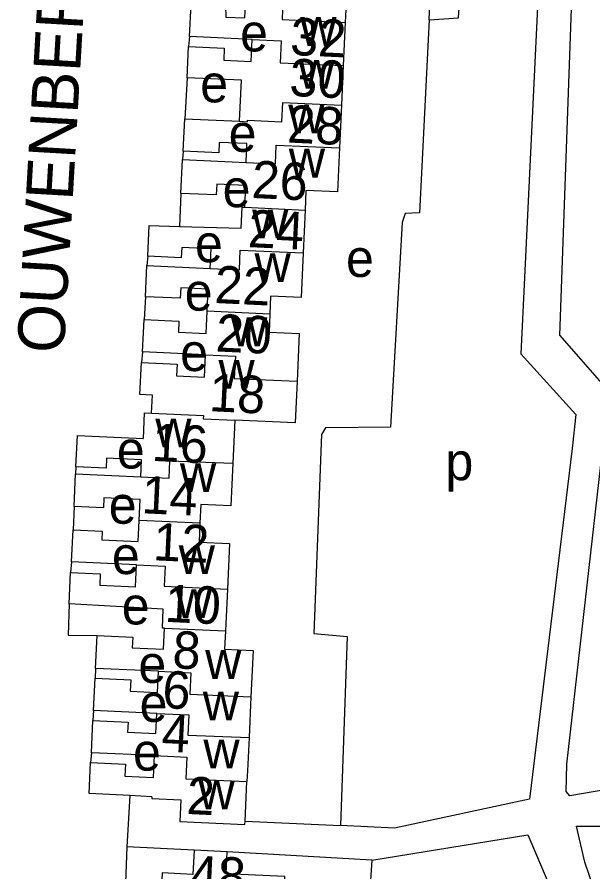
# Model space of a CAD drawing. Extents: x 163026 to 166241, y 382475 to 384501.
# Drawn here: x 164523.5 to 164584.9, y 383742 to 383833.2 of the extents above; entities that cross this region are included whole.
import ezdxf

# ---------------------------------------------------------------- set-up
doc = ezdxf.new("R2010")
doc.units = 0
for name, color, linetype in [('BLT_Basislijn', 7, 'Continuous'), ('BLT_Bebouwing', 7, 'Continuous'), ('BLT_Centroide', 7, 'Continuous'), ('BLT_Huisnummer', 7, 'Continuous'), ('BLT_Huisnummer_ tussenligend', 7, 'Continuous'), ('BLT_Onderverdeling_panden', 7, 'Continuous'), ('BLT_Straatnaam', 7, 'Continuous')]:
    doc.layers.add(name, color=color, linetype=linetype)

msp = doc.modelspace()

# ---------------------------------------------------------------- linework, layer by layer
at = {"layer": 'BLT_Basislijn'}
for p, q in [((164541.896, 383831.104), (164541.781, 383830.036)), ((164541.629, 383826.713), (164541.396, 383822.332)), ((164541.227, 383818.876), (164541.132, 383817.996)), ((164540.975, 383814.376), (164540.836, 383810.848)), ((164537.454, 383807.67), (164537.354, 383806.661)), ((164537.203, 383803.35), (164537.052, 383800.912)), ((164536.895, 383797.47), (164536.764, 383796.325)), ((164529.782, 383785.201), (164529.739, 383784.433)), ((164529.58, 383780.952), (164529.466, 383778.486)), ((164529.309, 383775.064), (164529.211, 383773.926)), ((164531.878, 383763.683), (164531.818, 383762.65)), ((164531.66, 383759.183), (164531.589, 383758.124)), ((164531.432, 383754.691), (164531.332, 383753.652)), ((164535.525, 383750.12), (164535.214, 383744.654)), ((164547.826, 383747.404), (164557.994, 383746.91)), ((164535.214, 383744.654), (164534.789, 383734.184)), ((164542.379, 383744.282), (164535.214, 383744.654)), ((164561.354, 383743.226), (164545.927, 383744.118))]:
    msp.add_line(p, q, dxfattribs=at)
for points in [[(164589.125, 383751.219), (164582.465, 383750.072), (164582.095, 383750.55), (164582.146, 383753.456), (164586.671, 383793.224), (164581.394, 383799.235), (164582.783, 383838.098), (164573.158, 383847.436), (164570.309, 383851.598)], [(164567.479, 383832.909), (164568.008, 383845.874), (164563.833, 383846.129)], [(164567.479, 383832.909), (164570.609, 383833.094), (164571.259, 383842.802), (164571.852, 383842.833), (164579.118, 383836.504), (164577.251, 383797.24), (164583.102, 383790.77), (164582.732, 383787.137), (164578.162, 383749.721), (164563.757, 383746.63), (164557.994, 383746.91)], [(164567.479, 383832.909), (164566.447, 383812.283), (164564.917, 383812.238), (164564.598, 383811.269), (164563.342, 383789.419), (164556.395, 383789.368), (164555.98, 383788.654), (164555.164, 383767.428), (164558.721, 383767.078), (164557.994, 383746.91)], [(164529.058, 383770.583), (164528.949, 383767.235), (164532.038, 383767.181)], [(164584.939, 383718.245), (164586.206, 383736.75), (164584.064, 383743.009), (164583.198, 383746.853), (164590.249, 383746.86)], [(164561.354, 383743.226), (164577.984, 383745.916), (164582.222, 383736.004), (164581.211, 383719.232)], [(164561.354, 383743.226), (164560.117, 383724.499), (164558.492, 383687.931)]]:
    msp.add_lwpolyline(points, dxfattribs=at)
at = {"layer": 'BLT_Bebouwing'}
for p, q in [((164558.717, 383837.266), (164558.503, 383832.608)), ((164558.503, 383832.608), (164558.292, 383828.002)), ((164541.629, 383826.713), (164541.781, 383830.036)), ((164558.292, 383828.002), (164558.098, 383823.771)), ((164558.098, 383823.771), (164557.89, 383819.228)), ((164541.227, 383818.876), (164541.396, 383822.332)), ((164540.975, 383814.376), (164541.132, 383817.996)), ((164554.221, 383812.596), (164554.011, 383808.024)), ((164537.203, 383803.35), (164537.354, 383806.661)), ((164536.895, 383797.47), (164537.052, 383800.912)), ((164536.608, 383792.907), (164536.764, 383796.325)), ((164546.734, 383790.167), (164546.525, 383785.595)), ((164529.58, 383780.952), (164529.739, 383784.433)), ((164529.309, 383775.064), (164529.466, 383778.486)), ((164529.058, 383770.583), (164529.211, 383773.926)), ((164545.932, 383772.149), (164545.73, 383767.679)), ((164531.878, 383763.683), (164532.038, 383767.181)), ((164531.66, 383759.183), (164531.818, 383762.65)), ((164548.44, 383760.65), (164548.24, 383756.32)), ((164531.432, 383754.691), (164531.589, 383758.124)), ((164548.24, 383756.32), (164548.082, 383752.767)), ((164548.082, 383752.767), (164548.022, 383751.602)), ((164547.826, 383747.404), (164548.022, 383751.602)), ((164537.883, 383750), (164535.525, 383750.12)), ((164545.927, 383744.118), (164542.379, 383744.282))]:
    msp.add_line(p, q, dxfattribs=at)
for points in [[(164545.734, 383834.376), (164545.771, 383833.184), (164547.787, 383833.092), (164547.887, 383835.272)], [(164541.896, 383831.104), (164542.053, 383834.545), (164545.734, 383834.376)], [(164548.576, 383830.798), (164541.896, 383831.104)], [(164541.781, 383830.036), (164545.598, 383829.861), (164545.54, 383828.588), (164548.469, 383828.454), (164548.576, 383830.798)], [(164547.227, 383822.064), (164547.427, 383826.448), (164541.629, 383826.713)], [(164541.396, 383822.332), (164547.227, 383822.064)], [(164547.925, 383817.675), (164548.015, 383819.679), (164545.063, 383819.814), (164545.013, 383818.718), (164541.227, 383818.876)], [(164557.89, 383819.228), (164557.676, 383814.541), (164554.317, 383814.695), (164554.221, 383812.596)], [(164541.132, 383817.996), (164547.925, 383817.675)], [(164547.781, 383812.89), (164547.888, 383815.22), (164544.805, 383815.361), (164544.752, 383814.203), (164540.975, 383814.376)], [(164540.836, 383810.848), (164547.422, 383810.651), (164547.525, 383812.902), (164547.781, 383812.89)], [(164537.454, 383807.67), (164537.604, 383810.945), (164540.836, 383810.848)], [(164544.089, 383806.353), (164544.186, 383808.464), (164541.066, 383808.607), (164541.016, 383807.507), (164537.454, 383807.67)], [(164554.011, 383808.024), (164553.795, 383803.274), (164550.551, 383803.422), (164550.462, 383801.494)], [(164537.354, 383806.661), (164544.089, 383806.353)], [(164543.782, 383801.801), (164543.89, 383804.157), (164540.951, 383804.291), (164540.9, 383803.181), (164537.203, 383803.35)], [(164537.052, 383800.912), (164540.769, 383800.742), (164540.714, 383799.551), (164543.673, 383799.416), (164543.782, 383801.801)], [(164550.462, 383801.494), (164550.374, 383799.567), (164553.596, 383799.42), (164553.363, 383794.332)], [(164543.606, 383797.163), (164536.895, 383797.47)], [(164536.764, 383796.325), (164540.576, 383796.15), (164540.52, 383794.914), (164543.497, 383794.778), (164543.606, 383797.163)], [(164553.363, 383794.332), (164553.16, 383789.873), (164546.734, 383790.167)], [(164537.845, 383790.93), (164537.933, 383792.846), (164536.608, 383792.907)], [(164529.782, 383785.201), (164529.939, 383788.549), (164536.971, 383788.224), (164537.096, 383790.964), (164537.845, 383790.93)], [(164536.695, 383784.115), (164536.781, 383785.96), (164533.049, 383786.13), (164533, 383785.057), (164529.782, 383785.201)], [(164546.525, 383785.595), (164546.316, 383781.026), (164543.089, 383781.174), (164542.997, 383779.173)], [(164529.739, 383784.433), (164536.695, 383784.115)], [(164536.509, 383779.47), (164536.611, 383781.7), (164532.766, 383781.876), (164532.717, 383780.809), (164529.58, 383780.952)], [(164529.466, 383778.486), (164532.579, 383778.344), (164532.536, 383777.405), (164536.406, 383777.228), (164536.509, 383779.47)], [(164542.997, 383779.173), (164542.906, 383777.172), (164546.157, 383777.023), (164545.932, 383772.149)], [(164529.211, 383773.926), (164532.367, 383773.782), (164532.312, 383772.569), (164536.147, 383772.393), (164536.255, 383774.745)], [(164536.255, 383774.745), (164529.309, 383775.064)], [(164539.229, 383767.978), (164538.995, 383767.988), (164539.088, 383770.011), (164529.058, 383770.583)], [(164532.038, 383767.181), (164535.833, 383767.008), (164535.781, 383765.892), (164539.126, 383765.739), (164539.229, 383767.978)], [(164545.73, 383767.679), (164545.642, 383765.747), (164548.67, 383765.608), (164548.44, 383760.65)], [(164538.595, 383763.375), (164531.878, 383763.683)], [(164531.818, 383762.65), (164535.628, 383762.476), (164535.572, 383761.243), (164538.492, 383761.11), (164538.595, 383763.375)], [(164538.395, 383758.875), (164531.66, 383759.183)], [(164531.589, 383758.124), (164535.34, 383757.952), (164535.291, 383756.867), (164538.299, 383756.729), (164538.395, 383758.875)], [(164538.157, 383754.384), (164531.432, 383754.691)], [(164535.525, 383750.12), (164531.175, 383750.341), (164531.332, 383753.652)], [(164531.332, 383753.652), (164535.061, 383753.481), (164535.002, 383752.201), (164538.051, 383752.061), (164538.157, 383754.384)], [(164537.883, 383750), (164537.875, 383749.791), (164540.979, 383749.648), (164540.874, 383747.36), (164547.808, 383747.032), (164547.826, 383747.404)], [(164542.379, 383744.282), (164542.26, 383741.707), (164538.964, 383741.859), (164538.859, 383739.588), (164542.073, 383739.44)], [(164551.836, 383736.616), (164552.06, 383741.489), (164545.819, 383741.777), (164545.927, 383744.118)]]:
    msp.add_lwpolyline(points, dxfattribs=at)
at = {"layer": 'BLT_Onderverdeling_panden'}
for p, q in [((164547.781, 383812.89), (164554.221, 383812.596)), ((164550.462, 383801.494), (164543.782, 383801.801)), ((164542.997, 383779.173), (164536.509, 383779.47)), ((164539.229, 383767.978), (164545.73, 383767.679))]:
    msp.add_line(p, q, dxfattribs=at)
for points in [[(164547.887, 383835.272), (164551.863, 383835.096), (164551.763, 383832.913), (164558.503, 383832.608)], [(164548.576, 383830.798), (164551.66, 383830.659), (164551.552, 383828.313), (164558.292, 383828.002)], [(164547.227, 383822.064), (164548.076, 383822.025), (164548.083, 383822.182), (164551.739, 383822.014), (164551.832, 383824.057), (164558.098, 383823.771)], [(164547.925, 383817.675), (164551.058, 383817.527), (164551.15, 383819.536), (164557.89, 383819.228)], [(164544.089, 383806.353), (164547.214, 383806.214), (164547.312, 383808.325), (164554.011, 383808.024)], [(164543.606, 383797.163), (164546.786, 383797.02), (164546.675, 383794.636), (164553.363, 383794.332)], [(164537.845, 383790.93), (164543.371, 383790.677), (164543.354, 383790.32), (164546.734, 383790.167)], [(164536.695, 383784.115), (164539.716, 383783.976), (164539.799, 383785.822), (164546.525, 383785.595)], [(164536.255, 383774.745), (164539.296, 383774.605), (164539.199, 383772.456), (164545.932, 383772.149)], [(164538.595, 383763.375), (164542.029, 383763.216), (164541.924, 383760.951), (164548.44, 383760.65)], [(164538.395, 383758.875), (164541.821, 383758.717), (164541.722, 383756.576), (164548.24, 383756.32)], [(164538.157, 383754.384), (164541.613, 383754.228), (164541.505, 383751.901), (164548.022, 383751.602)]]:
    msp.add_lwpolyline(points, dxfattribs=at)

# ---------------------------------------------------------------- texts
at = {"layer": 'BLT_Centroide'}
for s, p in [('w', (164553.708, 383830.106)), ('e', (164547.288, 383829.521)), ('w', (164553.515, 383825.548)), ('e', (164543.035, 383824.085)), ('w', (164552.424, 383820.781)), ('e', (164546.068, 383818.811)), ('w', (164552.488, 383816.062)), ('e', (164545.426, 383812.902)), ('w', (164548.572, 383809.562)), ('e', (164542.473, 383807.027)), ('e', (164558.586, 383805.455)), ('w', (164548.829, 383804.906)), ('e', (164541.382, 383801.86)), ('w', (164546.325, 383798.062)), ('e', (164540.895, 383795.415)), ('w', (164544.984, 383793.531)), ('w', (164538.242, 383787.281)), ('e', (164534.141, 383785.017)), ('p', (164569.196, 383783.766)), ('w', (164540.869, 383782.5)), ('e', (164533.275, 383779.125)), ('e', (164533.615, 383773.752)), ('w', (164540.74, 383773.743)), ('w', (164540.419, 383769.057)), ('e', (164534.66, 383768.38)), ('w', (164543.565, 383762.573)), ('e', (164536.439, 383762.141)), ('e', (164536.568, 383757.981)), ('w', (164543.308, 383758.144)), ('e', (164535.861, 383752.782)), ('w', (164543.372, 383753.008)), ('w', (164542.859, 383748.643))]:
    msp.add_text(s, height=4, dxfattribs=at).set_placement(p)
at = {"layer": 'BLT_Huisnummer'}
for s, rotation, p in [('30', 357.29175, (164552.497, 383824.784)), ('26', 357.29175, (164548.465, 383813.891)), ('22', 357.29175, (164544.506, 383802.683)), ('18', 357.29175, (164543.925, 383791.142)), ('14', 357.29175, (164536.716, 383780.249)), ('10', 357.29175, (164539.195, 383768.663)), ('6', 357.29175, (164538.935, 383759.459)), ('2', 357.29175, (164541.52, 383748.163)), ('48', 357.36549, (164541.846, 383739.743))]:
    msp.add_text(s, height=4, rotation=rotation, dxfattribs=at).set_placement(p)
at = {"layer": 'BLT_Huisnummer_ tussenligend'}
for s, p in [('32', (164552.58, 383829.155)), ('28', (164552.265, 383819.81)), ('24', (164548.072, 383808.648)), ('20', (164544.631, 383797.516)), ('16', (164537.81, 383785.835)), ('12', (164537.949, 383775.233)), ('8', (164540.019, 383763.712)), ('4', (164538.852, 383754.825))]:
    msp.add_text(s, height=4, rotation=357.29175, dxfattribs=at).set_placement(p)
at = {"layer": 'BLT_Straatnaam'}
msp.add_text('OUWENBERG', height=5, rotation=86.68372, dxfattribs=at).set_placement((164528.476, 383797.231))

doc.saveas('drawing.dxf')
